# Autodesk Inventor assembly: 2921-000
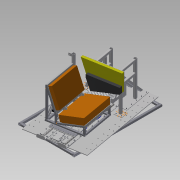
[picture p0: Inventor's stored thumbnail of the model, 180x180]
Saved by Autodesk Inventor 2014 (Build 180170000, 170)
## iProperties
Company: NHTSA/VRTC
Created: 2013-10
Part Number: 2921-000
Project: CHILD SIDE IMPACT SLED
Description: CHILD SIDE IMPACT SLED COMPLETE ASS'Y.
Document SubType Name: Assembly
Designer: DW
Title: Child Side Impact Sled Complete Ass'y.
Subject: Child Side Impact Sled
Author: Dave Walker
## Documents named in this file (3)
- B:\VRTC_DWG\BIO\Non-P572\Child Side-Frontal Impact Sled\Side Impact Sled\Child Side Impact Sled Complete Assembly.iam
- B:\VRTC_DWG\BIO\Non-P572\Child Side-Frontal Impact Sled\Side Impact Sled\Sub-Frame\Subframe Assembly.iam
- B:\VRTC_DWG\BIO\Non-P572\Child Side-Frontal Impact Sled\Side Impact Sled\Sled_Buck_Assembly.iam
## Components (2 placed, 2 different names)
1. Subframe Assembly:1 [sub-assembly] — Mate:1, Angle:1
2. Sled_Buck_Assembly:1 [sub-assembly] — Mate:1, Mate:2, Mate:3, Angle:1
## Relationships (4: Mate 3, Angle 1)
- Mate:1: Subframe Assembly:1 ↔ Sled_Buck_Assembly:1
- Mate:2: Sled_Buck_Assembly:1
- Mate:3: Sled_Buck_Assembly:1
- Angle:1: Subframe Assembly:1 ↔ Sled_Buck_Assembly:1
